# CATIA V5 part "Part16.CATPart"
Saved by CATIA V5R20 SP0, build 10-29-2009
Part number: 1bola238
Revision: ANY
Definition: UNKNOWN
Nomenclature: 1bola238
Source: Unknown
Bounding box of the stored display mesh (mm): x -1.19 to 1.19, y -1.19 to 1.19, z -1.19 to 1.19
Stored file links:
  C:\Users\Utente\Desktop\IO LAVORO\3D X SITO CF\CUMSA\3D files BA\BA 122024\Part16.CATPart
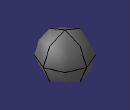
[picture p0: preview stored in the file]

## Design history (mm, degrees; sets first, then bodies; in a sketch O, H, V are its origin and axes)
Body1 "Revolución1" (main body)
  Solid1: solid without history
